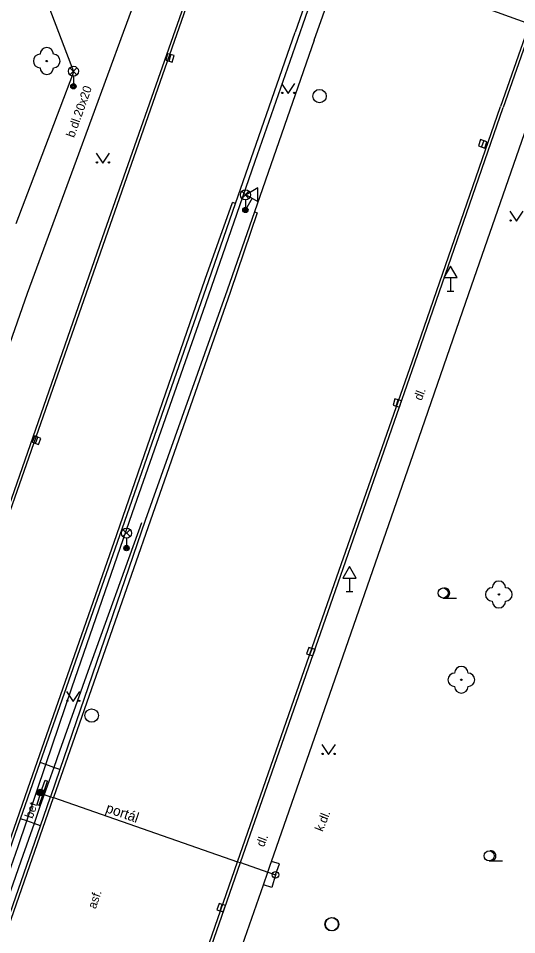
# Model space of a CAD drawing. Extents: x -598932 to -598196, y -1162207 to -1161504.
# Drawn here: x -598604.5 to -598567.3, y -1162150.8 to -1162082.4 of the extents above; entities that cross this region are included whole.
import ezdxf

# ---------------------------------------------------------------- set-up
doc = ezdxf.new("R2010")
doc.units = 0
for name, color, linetype in [('Level 22', 7, 'Continuous'), ('Level 25', 7, 'Continuous'), ('Level 27', 7, 'Continuous'), ('Level 33', 7, 'Continuous'), ('Level 34', 7, 'Continuous'), ('Level 36', 7, 'Continuous'), ('specificka linie pasportu komunikaci', 7, 'Continuous'), ('TM - chodniky - NP', 7, 'Continuous'), ('TM - chodniky - VP', 7, 'Continuous'), ('TM - DSPS - pomocna konstrukcna linie', 7, 'Continuous'), ('TM - komunikace - VP', 7, 'Continuous'), ('TM - plot dreveny_ kovovy - VP', 7, 'Continuous'), ('TM - popis povrchu', 7, 'Continuous'), ('TM - poznamka', 7, 'Continuous'), ('TM - rozhrani ploch obecne - NP', 7, 'Continuous'), ('TM - rozhrani ploch obecne - VP', 7, 'Continuous'), ('TM - svodidlo jednostranne - VP', 7, 'Continuous')]:
    doc.layers.add(name, color=color, linetype=linetype)

msp = doc.modelspace()

# ---------------------------------------------------------------- linework, layer by layer
at = {"layer": 'Level 22'}
for centre in [(-598602.38, -1162085.55), (-598568.65, -1162125.38), (-598571.45, -1162131.75)]:
    msp.add_circle(centre, 0.05, dxfattribs=at)
for centre, start, end in [((-598602.38, -1162085.05), 0, 180), ((-598602.88, -1162085.55), 90, 270), ((-598601.88, -1162085.55), 270, 90), ((-598602.38, -1162086.05), 180, 0), ((-598568.65, -1162124.88), 0, 180), ((-598569.15, -1162125.38), 90, 270), ((-598568.15, -1162125.38), 270, 90), ((-598568.65, -1162125.88), 180, 0), ((-598571.45, -1162131.25), 0, 180), ((-598571.95, -1162131.75), 90, 270), ((-598570.95, -1162131.75), 270, 90), ((-598571.45, -1162132.25), 180, 0)]:
    msp.add_arc(centre, 0.5, start, end, dxfattribs=at)
at = {"layer": 'Level 25'}
for centre, radius in [((-598602.86, -1162140.17), 0.25), ((-598602.86, -1162140.17), 0.2), ((-598602.86, -1162140.17), 0.15), ((-598602.86, -1162140.17), 0.1), ((-598602.86, -1162140.17), 0.05), ((-598585.32, -1162146.31), 0.25), ((-598585.32, -1162146.31), 0.0303)]:
    msp.add_circle(centre, radius, dxfattribs=at)
at = {"layer": 'Level 27'}
for p, q in [((-598593.258, -1162085.561), (-598593.122, -1162085.079)), ((-598569.778, -1162091.494), (-598569.942, -1162091.966)), ((-598576.301, -1162111.32), (-598576.159, -1162110.84)), ((-598603.232, -1162114.103), (-598603.048, -1162113.637)), ((-598582.755, -1162129.885), (-598582.585, -1162129.415)), ((-598589.449, -1162148.997), (-598589.291, -1162148.523))]:
    msp.add_line(p, q, dxfattribs=at)
for points in [[(-598593.017, -1162085.628), (-598592.882, -1162085.147), (-598593.363, -1162085.012), (-598593.498, -1162085.493)], [(-598570.014, -1162091.412), (-598570.178, -1162091.884), (-598569.706, -1162092.048), (-598569.542, -1162091.576)], [(-598576.061, -1162111.39), (-598575.92, -1162110.911), (-598576.399, -1162110.77), (-598576.54, -1162111.249)], [(-598602.999, -1162114.194), (-598602.816, -1162113.729), (-598603.281, -1162113.546), (-598603.464, -1162114.011)], [(-598582.52, -1162129.97), (-598582.35, -1162129.5), (-598582.82, -1162129.33), (-598582.99, -1162129.8)], [(-598589.212, -1162149.076), (-598589.054, -1162148.602), (-598589.528, -1162148.444), (-598589.686, -1162148.918)]]:
    msp.add_lwpolyline(points, close=True, dxfattribs=at)
for centre in [(-598582.03, -1162088.17), (-598599.03, -1162134.42), (-598581.13, -1162150)]:
    msp.add_circle(centre, 0.5, dxfattribs=at)
at = {"layer": 'Level 33'}
for p, q in [((-598600.655, -1162086.58), (-598600.125, -1162086.05)), ((-598600.655, -1162086.05), (-598600.125, -1162086.58)), ((-598600.39, -1162086.69), (-598600.39, -1162087.44)), ((-598587.825, -1162095.81), (-598587.295, -1162095.28)), ((-598587.825, -1162095.28), (-598587.295, -1162095.81)), ((-598587.56, -1162095.92), (-598587.56, -1162096.67)), ((-598596.695, -1162121.06), (-598596.165, -1162120.53)), ((-598596.695, -1162120.53), (-598596.165, -1162121.06)), ((-598596.43, -1162121.17), (-598596.43, -1162121.92))]:
    msp.add_line(p, q, dxfattribs=at)
for centre, radius in [((-598600.39, -1162086.315), 0.375), ((-598600.39, -1162087.44), 0.2), ((-598600.39, -1162087.44), 0.145), ((-598600.39, -1162087.44), 0.0876), ((-598587.56, -1162095.545), 0.375), ((-598587.56, -1162096.67), 0.2), ((-598587.56, -1162096.67), 0.145), ((-598587.56, -1162096.67), 0.0876), ((-598596.43, -1162120.795), 0.375), ((-598596.43, -1162121.92), 0.2), ((-598596.43, -1162121.92), 0.145), ((-598596.43, -1162121.92), 0.0876)]:
    msp.add_circle(centre, radius, dxfattribs=at)
at = {"layer": 'Level 34'}
for p, q in [((-598587.061, -1162095.783), (-598587.56, -1162096.67)), ((-598587.778, -1162096.547), (-598587.342, -1162096.793)), ((-598572.26, -1162101.722), (-598572.26, -1162102.74)), ((-598572.51, -1162102.74), (-598572.01, -1162102.74)), ((-598579.8, -1162124.152), (-598579.8, -1162125.17)), ((-598580.05, -1162125.17), (-598579.55, -1162125.17))]:
    msp.add_line(p, q, dxfattribs=at)
for points in [[(-598587.496, -1162095.538), (-598586.625, -1162096.028), (-598586.636, -1162095.028)], [(-598572.76, -1162101.722), (-598571.76, -1162101.722), (-598572.26, -1162100.856)], [(-598580.3, -1162124.152), (-598579.3, -1162124.152), (-598579.8, -1162123.286)]]:
    msp.add_lwpolyline(points, close=True, dxfattribs=at)
at = {"layer": 'Level 36'}
for p, q in [((-598572.81, -1162125.645), (-598571.81, -1162125.645)), ((-598569.37, -1162145.275), (-598568.37, -1162145.275))]:
    msp.add_line(p, q, dxfattribs=at)
for points in [[(-598584.86, -1162087.23), (-598584.36, -1162087.98), (-598583.86, -1162087.23)], [(-598598.69, -1162092.42), (-598598.19, -1162093.17), (-598597.69, -1162092.42)], [(-598567.83, -1162096.76), (-598567.33, -1162097.51), (-598566.83, -1162096.76)], [(-598600.9, -1162132.62), (-598600.4, -1162133.37), (-598599.9, -1162132.62)], [(-598581.85, -1162136.59), (-598581.35, -1162137.34), (-598580.85, -1162136.59)]]:
    msp.add_lwpolyline(points, dxfattribs=at)
for centre, radius in [((-598584.81, -1162087.93), 0.05), ((-598583.911, -1162087.93), 0.05), ((-598598.64, -1162093.12), 0.05), ((-598597.741, -1162093.12), 0.05), ((-598567.78, -1162097.46), 0.05), ((-598572.81, -1162125.27), 0.375), ((-598600.85, -1162133.32), 0.05), ((-598599.951, -1162133.32), 0.05), ((-598581.8, -1162137.29), 0.05), ((-598580.901, -1162137.29), 0.05), ((-598569.37, -1162144.9), 0.375)]:
    msp.add_circle(centre, radius, dxfattribs=at)
for centre in [(-598572.685, -1162125.27), (-598569.245, -1162144.9)]:
    msp.add_arc(centre, 0.375, 260.40593, 99.59407, dxfattribs=at)
at = {"layer": 'specificka linie pasportu komunikaci'}
msp.add_lwpolyline([(-598581.043, -1162150.493), (-598581.241, -1162150.472), (-598581.415, -1162150.376), (-598581.538, -1162150.219), (-598581.59, -1162150.027), (-598581.563, -1162149.83), (-598581.461, -1162149.659), (-598581.301, -1162149.541), (-598581.107, -1162149.495), (-598580.911, -1162149.529), (-598580.743, -1162149.636), (-598580.631, -1162149.8), (-598580.591, -1162149.995), (-598580.61, -1162150.13), (-598580.7, -1162150.307), (-598580.853, -1162150.435), (-598581.043, -1162150.493)], dxfattribs=at)
at = {"layer": 'TM - chodniky - NP'}
msp.add_lwpolyline([(-598580.21, -1162077.74), (-598566.36, -1162082.78)], dxfattribs=at)
at = {"layer": 'TM - chodniky - VP'}
for points in [[(-598591.24, -1162075.6), (-598595.59, -1162080.43), (-598596.69, -1162083.41)], [(-598604.67, -1162097.67), (-598601.379, -1162089.054), (-598600.35, -1162086.36), (-598602.19, -1162081.52), (-598601.27, -1162079.69)], [(-598596.69, -1162083.41), (-598600.197, -1162092.988), (-598603.83, -1162102.91), (-598607.233, -1162112.549), (-598617.63, -1162142)], [(-598585.89, -1162146.11), (-598585.7, -1162145.58), (-598585.61, -1162145.31), (-598581.26, -1162132.82), (-598576.27, -1162118.43), (-598574.63, -1162113.71), (-598570.89, -1162102.92), (-598564.38, -1162084.18)], [(-598593.69, -1162201.01), (-598594.98, -1162200.61), (-598596.17, -1162199.97), (-598597.01, -1162199.35), (-598597.63, -1162198.82), (-598598.25, -1162198.21), (-598598.92, -1162197.47), (-598599.65, -1162196.43), (-598600.17, -1162195.43), (-598600.57, -1162194.32), (-598600.83, -1162193.12), (-598600.95, -1162191.66), (-598600.9, -1162190.34), (-598600.67, -1162188.93), (-598600.31, -1162187.63), (-598599.888, -1162186.403), (-598599.32, -1162184.75), (-598598.33, -1162181.88), (-598597.21, -1162178.63), (-598593.97, -1162169.32), (-598590.73, -1162160), (-598586.22, -1162147.06), (-598585.89, -1162146.11)]]:
    msp.add_lwpolyline(points, dxfattribs=at)
at = {"layer": 'TM - DSPS - pomocna konstrukcna linie'}
for points in [[(-598602.84, -1162140.21), (-598602.5, -1162139.25), (-598602.33, -1162139.31)], [(-598602.66, -1162140.28), (-598602.33, -1162139.31)], [(-598602.84, -1162140.21), (-598603.13, -1162141.05), (-598602.95, -1162141.11), (-598602.66, -1162140.28)], [(-598585.32, -1162146.31), (-598585.02, -1162145.49), (-598585.61, -1162145.31)], [(-598585.32, -1162146.31), (-598585.59, -1162147.27), (-598586.22, -1162147.06)]]:
    msp.add_lwpolyline(points, dxfattribs=at)
at = {"layer": 'TM - komunikace - VP'}
for points in [[(-598581.68, -1162077.21), (-598581.8, -1162077.55), (-598583.85, -1162083.4)], [(-598582.42, -1162083.99), (-598580.36, -1162078.16), (-598580.21, -1162077.74)], [(-598608.35, -1162127.72), (-598604.78, -1162117.61), (-598598.22, -1162098.74), (-598591.99, -1162080.94)], [(-598566.17, -1162082.85), (-598566.35, -1162083.35), (-598568.34, -1162089.02)], [(-598588.3, -1162096.19), (-598583.85, -1162083.4)], [(-598582.42, -1162083.99), (-598586.87, -1162096.81)], [(-598587.93, -1162145.4), (-598581.22, -1162126.15), (-598574.93, -1162108.09), (-598568.34, -1162089.02)], [(-598602.88, -1162137.92), (-598596.94, -1162120.97), (-598590.3, -1162101.93), (-598588.3, -1162096.19)], [(-598586.87, -1162096.81), (-598588.91, -1162102.67), (-598595.03, -1162119.86), (-598601.4, -1162138.46)], [(-598604.34, -1162142.13), (-598602.88, -1162137.92)], [(-598601.4, -1162138.46), (-598602.09, -1162140.48)], [(-598602.85, -1162142.65), (-598602.09, -1162140.48)], [(-598616.67, -1162177.49), (-598609.8, -1162157.81), (-598604.34, -1162142.13)], [(-598624.794, -1162206.96), (-598621.59, -1162196.99), (-598619.16, -1162189.65), (-598615.15, -1162177.92), (-598608.61, -1162159.2), (-598602.85, -1162142.65)], [(-598601.26, -1162183.73), (-598594.44, -1162164.13), (-598587.93, -1162145.4)]]:
    msp.add_lwpolyline(points, dxfattribs=at)
at = {"layer": 'TM - plot dreveny_ kovovy - VP'}
for points in [[(-598587.98, -1162096.33), (-598586.83, -1162093.03), (-598584.23, -1162085.56), (-598581.37, -1162077.32)], [(-598602.44, -1162138.08), (-598600.5, -1162132.35), (-598595.98, -1162119.27), (-598590.72, -1162104.23), (-598587.98, -1162096.33)], [(-598603.87, -1162142.29), (-598602.44, -1162138.08)], [(-598625.185, -1162206.96), (-598625, -1162206.36), (-598622.57, -1162198.85), (-598618.79, -1162187.52), (-598616.03, -1162179.39), (-598612.19, -1162168.43), (-598612.14, -1162166.13), (-598608.2, -1162154.66), (-598604.51, -1162144.2), (-598603.87, -1162142.29)]]:
    msp.add_lwpolyline(points, dxfattribs=at)
at = {"layer": 'TM - rozhrani ploch obecne - NP'}
for points in [[(-598602.84, -1162140.21), (-598602.66, -1162140.28)], [(-598602.66, -1162140.28), (-598602.57, -1162140.31)], [(-598602.57, -1162140.31), (-598602.09, -1162140.48)], [(-598602.09, -1162140.48), (-598601.88, -1162140.55)], [(-598601.88, -1162140.55), (-598588.14, -1162145.33)], [(-598588.14, -1162145.33), (-598587.93, -1162145.4)], [(-598587.93, -1162145.4), (-598585.89, -1162146.11)], [(-598585.89, -1162146.11), (-598585.32, -1162146.31)]]:
    msp.add_lwpolyline(points, dxfattribs=at)
at = {"layer": 'TM - rozhrani ploch obecne - VP'}
for points in [[(-598608.17, -1162127.81), (-598604.58, -1162117.67), (-598597.99, -1162098.8), (-598591.77, -1162081)], [(-598566.36, -1162082.78), (-598566.54, -1162083.28), (-598568.53, -1162088.95)], [(-598588.14, -1162145.33), (-598581.43, -1162126.06), (-598575.13, -1162108.01), (-598568.53, -1162088.95)], [(-598603.78, -1162139.88), (-598597.16, -1162120.9), (-598590.55, -1162101.85), (-598588.52, -1162096.11)], [(-598588.3, -1162096.19), (-598588.52, -1162096.11)], [(-598586.87, -1162096.81), (-598586.67, -1162096.88), (-598588.68, -1162102.76), (-598601.88, -1162140.55)], [(-598602.44, -1162138.08), (-598602.88, -1162137.92)], [(-598601.86, -1162138.29), (-598602.44, -1162138.08)], [(-598601.4, -1162138.46), (-598601.86, -1162138.29)], [(-598626.703, -1162206.96), (-598626.35, -1162205.84), (-598623.58, -1162197.32), (-598620.04, -1162186.69), (-598616.88, -1162177.43), (-598610.34, -1162158.65), (-598603.78, -1162139.88)], [(-598624.542, -1162206.96), (-598621.37, -1162197.08), (-598617.92, -1162186.71), (-598614.95, -1162178.01), (-598608.42, -1162159.28), (-598601.88, -1162140.55)], [(-598603.87, -1162142.29), (-598604.34, -1162142.13)], [(-598603.33, -1162142.48), (-598603.87, -1162142.29)], [(-598602.85, -1162142.65), (-598603.33, -1162142.48)], [(-598601.45, -1162183.65), (-598594.65, -1162164.05), (-598588.14, -1162145.33)]]:
    msp.add_lwpolyline(points, dxfattribs=at)
at = {"layer": 'TM - svodidlo jednostranne - VP'}
for points in [[(-598595.32, -1162120.03), (-598599.31, -1162131.14), (-598601.43, -1162137.08), (-598601.86, -1162138.29)], [(-598601.86, -1162138.29), (-598602.23, -1162139.35), (-598602.57, -1162140.31)], [(-598602.57, -1162140.31), (-598602.86, -1162141.14), (-598603.33, -1162142.48)], [(-598603.33, -1162142.48), (-598604.31, -1162145.28), (-598608.44, -1162157.08), (-598610.08, -1162161.8)]]:
    msp.add_lwpolyline(points, dxfattribs=at)

# ---------------------------------------------------------------- texts
at = {"layer": 'TM - popis povrchu'}
for s, rotation, p in [('b.dl.20x20', 70.47, (-598600.34, -1162091.32)), ('dl.', 68.73, (-598574.42, -1162110.95)), ('bet.', 70.81, (-598603.44, -1162142.16)), ('k.dl.', 68.07, (-598581.8, -1162143.13)), ('dl.', 68.73, (-598586.18, -1162144.28)), ('asf.', 70.83, (-598598.73, -1162148.9))]:
    msp.add_text(s, height=0.65, rotation=rotation, dxfattribs=at).set_placement(p)
at = {"layer": 'TM - poznamka'}
msp.add_text('portál', height=0.75, rotation=341, dxfattribs=at).set_placement((-598598.04, -1162141.62))

doc.saveas('drawing.dxf')
